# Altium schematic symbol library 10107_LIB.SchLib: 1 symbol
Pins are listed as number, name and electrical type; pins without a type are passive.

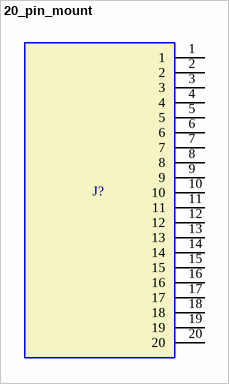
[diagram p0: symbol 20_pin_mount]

## 20_pin_mount
designator J?  (value not drawn)
pins: 1 "something", 2, 3, 4, 5, 6, 7, 8, 9, 10, 11, 12, 13, 14, 15, 16, 17, 18, 19, 20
